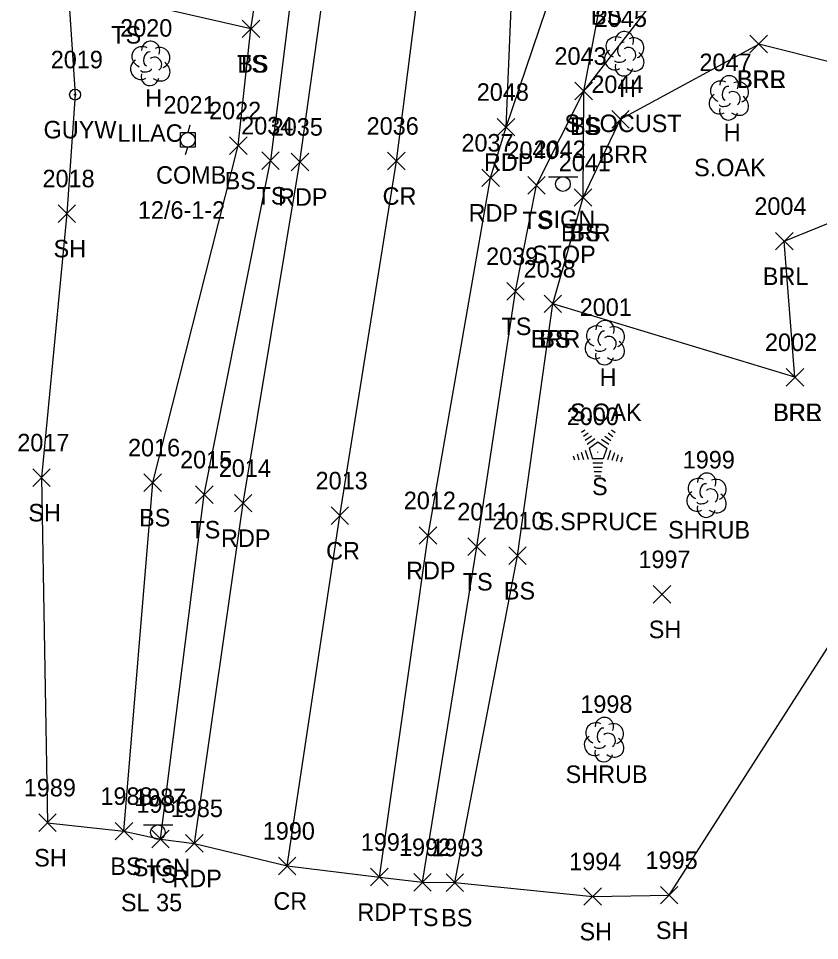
# Model space of a CAD drawing. Extents: x 1461855 to 1464118, y 556196 to 557441.
# Drawn here: x 1461894.8 to 1461986.2, y 556297.5 to 556402.7 of the extents above; entities that cross this region are included whole.
import ezdxf

# ---------------------------------------------------------------- set-up
doc = ezdxf.new("R2010")
doc.units = 0
for name, color, linetype in [('L_A', 7, 'Continuous'), ('L_C', 7, 'Continuous'), ('L_I', 7, 'Continuous'), ('L_TIC', 7, 'Continuous'), ('LABL', 7, 'Continuous'), ('LELB', 7, 'Continuous'), ('LSH', 7, 'Continuous'), ('LSOGP', 7, 'Continuous'), ('LTC', 7, 'Continuous'), ('LTD', 7, 'Continuous'), ('P_A', 7, 'Continuous'), ('P_I', 7, 'Continuous'), ('P_TIC', 7, 'Continuous'), ('PET', 7, 'Continuous'), ('PRC', 7, 'Continuous'), ('S_A', 7, 'Continuous'), ('S_C', 7, 'Continuous'), ('S_I', 7, 'Continuous'), ('SSGN', 7, 'Continuous'), ('U_A', 7, 'Continuous'), ('U_C', 7, 'Continuous'), ('U_I', 7, 'Continuous'), ('UP', 7, 'Continuous'), ('UPGW', 7, 'Continuous')]:
    doc.layers.add(name, color=color, linetype=linetype)

msp = doc.modelspace()

# ---------------------------------------------------------------- linework, layer by layer
at = {"layer": 'L_TIC'}
for points in [[(1461920.33, 556400.53), (1461922.33, 556402.53)], [(1461922.33, 556400.53), (1461920.33, 556402.53)], [(1461920.33, 556400.53), (1461922.33, 556402.53)], [(1461922.33, 556400.53), (1461920.33, 556402.53)], [(1461978.3, 556398.79), (1461980.3, 556400.79)], [(1461980.3, 556398.79), (1461978.3, 556400.79)], [(1461978.3, 556398.79), (1461980.3, 556400.79)], [(1461980.3, 556398.79), (1461978.3, 556400.79)], [(1461958.32, 556393.42), (1461960.32, 556395.42)], [(1461960.32, 556393.42), (1461958.32, 556395.42)], [(1461958.32, 556393.42), (1461960.32, 556395.42)], [(1461960.32, 556393.42), (1461958.32, 556395.42)], [(1461962.52, 556390.2), (1461964.52, 556392.2)], [(1461964.52, 556390.2), (1461962.52, 556392.2)], [(1461918.89, 556387.2), (1461920.89, 556389.2)], [(1461920.89, 556387.2), (1461918.89, 556389.2)], [(1461922.56, 556385.47), (1461924.56, 556387.47)], [(1461924.56, 556385.47), (1461922.56, 556387.47)], [(1461922.56, 556385.47), (1461924.56, 556387.47)], [(1461924.56, 556385.47), (1461922.56, 556387.47)], [(1461952.93, 556382.67), (1461954.93, 556384.67)], [(1461954.93, 556382.67), (1461952.93, 556384.67)], [(1461958.24, 556381.28), (1461960.24, 556383.28)], [(1461960.24, 556381.28), (1461958.24, 556383.28)], [(1461958.24, 556381.28), (1461960.24, 556383.28)], [(1461960.24, 556381.28), (1461958.24, 556383.28)], [(1461899.31, 556379.44), (1461901.31, 556381.44)], [(1461901.31, 556379.44), (1461899.31, 556381.44)], [(1461981.22, 556376.29), (1461983.22, 556378.29)], [(1461983.22, 556376.29), (1461981.22, 556378.29)], [(1461950.53, 556370.57), (1461952.53, 556372.57)], [(1461952.53, 556370.57), (1461950.53, 556372.57)], [(1461954.8, 556369.14), (1461956.8, 556371.14)], [(1461956.8, 556369.14), (1461954.8, 556371.14)], [(1461954.8, 556369.14), (1461956.8, 556371.14)], [(1461956.8, 556369.14), (1461954.8, 556371.14)], [(1461982.43, 556360.75), (1461984.43, 556362.75)], [(1461984.43, 556360.75), (1461982.43, 556362.75)], [(1461982.43, 556360.75), (1461984.43, 556362.75)], [(1461984.43, 556360.75), (1461982.43, 556362.75)], [(1461896.43, 556349.3), (1461898.43, 556351.3)], [(1461898.43, 556349.3), (1461896.43, 556351.3)], [(1461909.12, 556348.73), (1461911.12, 556350.73)], [(1461911.12, 556348.73), (1461909.12, 556350.73)], [(1461915.01, 556347.36), (1461917.01, 556349.36)], [(1461917.01, 556347.36), (1461915.01, 556349.36)], [(1461946.1, 556341.42), (1461948.1, 556343.42)], [(1461948.1, 556341.42), (1461946.1, 556343.42)], [(1461950.76, 556340.39), (1461952.76, 556342.39)], [(1461952.76, 556340.39), (1461950.76, 556342.39)], [(1461967.25, 556335.98), (1461969.25, 556337.98)], [(1461969.25, 556335.98), (1461967.25, 556337.98)], [(1461897.1, 556309.92), (1461899.1, 556311.92)], [(1461899.1, 556309.92), (1461897.1, 556311.92)], [(1461905.84, 556308.95), (1461907.84, 556310.95)], [(1461907.84, 556308.95), (1461905.84, 556310.95)], [(1461910.01, 556308.05), (1461912.01, 556310.05)], [(1461912.01, 556308.05), (1461910.01, 556310.05)], [(1461939.92, 556303.12), (1461941.92, 556305.12)], [(1461941.92, 556303.12), (1461939.92, 556305.12)], [(1461943.6, 556303.08), (1461945.6, 556305.08)], [(1461945.6, 556303.08), (1461943.6, 556305.08)], [(1461959.35, 556301.49), (1461961.35, 556303.49)], [(1461961.35, 556301.49), (1461959.35, 556303.49)], [(1461968.08, 556301.64), (1461970.08, 556303.64)], [(1461970.08, 556301.64), (1461968.08, 556303.64)]]:
    msp.add_lwpolyline(points, dxfattribs=at)
at = {"layer": 'LABL'}
for points in [[(1461983.43, 556361.75), (1461955.8, 556370.14), (1461959.24, 556382.28), (1461963.52, 556391.2), (1461979.3, 556399.79)], [(1461983.43, 556361.75), (1461982.22, 556377.29), (1461996.74, 556383.18), (1461996.43, 556395.47), (1461979.3, 556399.79)]]:
    msp.add_lwpolyline(points, dxfattribs=at)
at = {"layer": 'LELB'}
for points in [[(1461959.24, 556382.28), (1461959.32, 556394.42), (1461961.7, 556406.99), (1461971.62, 556419.74), (1461999.37, 556433.49)], [(1461921.33, 556401.53), (1461906.98, 556404.84), (1461899.53, 556420.36), (1461906.98, 556423.45), (1461923.2, 556423.61), (1461927.16, 556415.18), (1461923.56, 556386.47)], [(1461906.84, 556309.95), (1461910.12, 556349.73), (1461919.89, 556388.2), (1461921.33, 556401.53), (1461922.52, 556409.21), (1461920.13, 556420.53)], [(1461940.92, 556304.12), (1461947.1, 556342.42), (1461951.53, 556371.57), (1461953.93, 556383.67), (1461959.32, 556394.42), (1461975.32, 556415.02), (1461996.03, 556418.95)], [(1461911.01, 556309.05), (1461916.01, 556348.36), (1461923.56, 556386.47)], [(1461944.6, 556304.08), (1461951.76, 556341.39), (1461955.8, 556370.14)]]:
    msp.add_lwpolyline(points, dxfattribs=at)
at = {"layer": 'LSH'}
for p, q in [((1461973.32, 556348.35), (1461973.32, 556348.35)), ((1461973.32, 556348.35), (1461973.32, 556348.35)), ((1461961.62, 556320.45), (1461961.62, 556320.45)), ((1461961.62, 556320.45), (1461961.62, 556320.45))]:
    msp.add_line(p, q, dxfattribs=at)
for centre in [(1461973.36, 556349.78), (1461961.67, 556321.89)]:
    msp.add_arc(centre, 1.05, 335.5272, 180.9563, dxfattribs=at)
for centre, major_axis, ratio, start_param, end_param in [((1461972.53, 556349.01), (1.21, -0.51), 0.895232, 1.570796, 4.712389), ((1461973.11, 556348.81), (-0.208, -0.792), 0.645439, 3.141593, 6.283185), ((1461974.36, 556348.93), (-1.14, -0.48), 0.949671, 1.570796, 4.712389), ((1461972.23, 556347.64), (0.58, -1.04), 0.959034, 3.141593, 6.283185), ((1461973.82, 556348.18), (-0.5, 0.667), 0.989748, 3.141593, 6.283185), ((1461972.86, 556347.6), (-0.625, -0.083), 0.423636, 0, 3.141593), ((1461974.32, 556347.51), (-1.09, 0.79), 0.841452, 1.570796, 4.712389), ((1461973.32, 556346.85), (0.26, 1.06), 0.942809, 1.570796, 4.712389), ((1461960.83, 556321.12), (1.21, -0.51), 0.895232, 1.570796, 4.712389), ((1461962.66, 556321.04), (-1.14, -0.48), 0.949671, 1.570796, 4.712389), ((1461961.41, 556320.91), (-0.208, -0.792), 0.645439, 3.141593, 6.283185), ((1461960.54, 556319.75), (0.58, -1.04), 0.959034, 3.141593, 6.283185), ((1461962.12, 556320.29), (-0.5, 0.667), 0.989748, 3.141593, 6.283185), ((1461962.62, 556319.62), (-1.09, 0.79), 0.841452, 1.570796, 4.712389), ((1461961.62, 556318.95), (0.26, 1.06), 0.942809, 1.570796, 4.712389), ((1461961.16, 556319.7), (-0.625, -0.083), 0.423636, 0, 3.141593)]:
    msp.add_ellipse(centre, major_axis=major_axis, ratio=ratio, start_param=start_param, end_param=end_param, dxfattribs=at)
at = {"layer": 'LSOGP'}
msp.add_lwpolyline([(1461899.53, 556420.36), (1461901.26, 556394.02), (1461900.31, 556380.44), (1461897.43, 556350.3), (1461898.1, 556310.92), (1461906.84, 556309.95), (1461911.01, 556309.05), (1461914.87, 556308.56), (1461925.46, 556305.98), (1461935.99, 556304.71), (1461940.92, 556304.12), (1461944.6, 556304.08), (1461960.35, 556302.49), (1461969.08, 556302.64), (1461988.94, 556333.66), (1462002.21, 556358.85), (1462020.07, 556368.85), (1462042.96, 556370.97)], dxfattribs=at)
at = {"layer": 'LTC'}
for p, q in [((1461959.08, 556355.5), (1461959.43, 556355.76)), ((1461959.29, 556355.04), (1461959.82, 556355.42)), ((1461959.5, 556354.57), (1461960.2, 556355.08)), ((1461961.73, 556355.05), (1461962.41, 556354.55)), ((1461962.11, 556355.4), (1461962.66, 556355)), ((1461962.48, 556355.75), (1461962.9, 556355.44)), ((1461959.71, 556354.11), (1461960.59, 556354.75)), ((1461959.93, 556353.65), (1461960.94, 556354.39)), ((1461960.94, 556354.39), (1461961.94, 556353.66)), ((1461961.36, 556354.7), (1461962.17, 556354.11)), ((1461958.57, 556353), (1461958.78, 556352.35)), ((1461959.02, 556353.22), (1461959.29, 556352.38)), ((1461959.48, 556353.43), (1461959.81, 556352.41)), ((1461959.93, 556353.65), (1461960.32, 556352.46)), ((1461961.94, 556353.66), (1461961.55, 556352.46)), ((1461962.38, 556353.39), (1461962.04, 556352.35)), ((1461962.82, 556353.14), (1461962.54, 556352.26)), ((1461963.27, 556352.89), (1461963.03, 556352.16)), ((1461958.11, 556352.78), (1461958.26, 556352.32)), ((1461961.55, 556352.46), (1461960.32, 556352.46)), ((1461961.51, 556351.96), (1461960.37, 556351.96)), ((1461963.71, 556352.64), (1461963.52, 556352.07)), ((1461961.43, 556351.46), (1461960.44, 556351.46)), ((1461961.34, 556350.96), (1461960.51, 556350.96)), ((1461961.26, 556350.46), (1461960.58, 556350.46))]:
    msp.add_line(p, q, dxfattribs=at)
at = {"layer": 'LTD'}
for p, q in [((1461963.93, 556398.74), (1461963.93, 556398.74)), ((1461963.93, 556398.74), (1461963.93, 556398.74)), ((1461909.82, 556397.63), (1461909.82, 556397.63)), ((1461909.82, 556397.63), (1461909.82, 556397.63)), ((1461975.87, 556393.7), (1461975.87, 556393.7)), ((1461975.87, 556393.7), (1461975.87, 556393.7)), ((1461961.71, 556365.76), (1461961.71, 556365.76)), ((1461961.71, 556365.76), (1461961.71, 556365.76))]:
    msp.add_line(p, q, dxfattribs=at)
for centre in [(1461963.97, 556400.17), (1461909.87, 556399.06), (1461975.92, 556395.13), (1461961.75, 556367.19)]:
    msp.add_arc(centre, 1.05, 335.5272, 180.9563, dxfattribs=at)
for centre, major_axis, ratio, start_param, end_param in [((1461963.14, 556399.41), (1.21, -0.51), 0.895232, 1.570796, 4.712389), ((1461964.97, 556399.32), (-1.14, -0.48), 0.949671, 1.570796, 4.712389), ((1461909.03, 556398.29), (1.21, -0.51), 0.895232, 1.570796, 4.712389), ((1461910.86, 556398.21), (-1.14, -0.48), 0.949671, 1.570796, 4.712389), ((1461963.72, 556399.2), (-0.208, -0.792), 0.645439, 3.141593, 6.283185), ((1461964.43, 556398.57), (-0.5, 0.667), 0.989748, 3.141593, 6.283185), ((1461909.61, 556398.09), (-0.208, -0.792), 0.645439, 3.141593, 6.283185), ((1461910.32, 556397.46), (-0.5, 0.667), 0.989748, 3.141593, 6.283185), ((1461962.84, 556398.03), (0.58, -1.04), 0.959034, 3.141593, 6.283185), ((1461964.93, 556397.91), (-1.09, 0.79), 0.841452, 1.570796, 4.712389), ((1461908.74, 556396.92), (0.58, -1.04), 0.959034, 3.141593, 6.283185), ((1461910.82, 556396.79), (-1.09, 0.79), 0.841452, 1.570796, 4.712389), ((1461963.93, 556397.24), (0.26, 1.06), 0.942809, 1.570796, 4.712389), ((1461963.47, 556397.99), (-0.625, -0.083), 0.423636, 0, 3.141593), ((1461909.82, 556396.13), (0.26, 1.06), 0.942809, 1.570796, 4.712389), ((1461909.36, 556396.88), (-0.625, -0.083), 0.423636, 0, 3.141593), ((1461975.08, 556394.37), (1.21, -0.51), 0.895232, 1.570796, 4.712389), ((1461975.66, 556394.16), (-0.208, -0.792), 0.645439, 3.141593, 6.283185), ((1461976.91, 556394.28), (-1.14, -0.48), 0.949671, 1.570796, 4.712389), ((1461974.79, 556392.99), (0.58, -1.04), 0.959034, 3.141593, 6.283185), ((1461976.37, 556393.53), (-0.5, 0.667), 0.989748, 3.141593, 6.283185), ((1461975.41, 556392.95), (-0.625, -0.083), 0.423636, 0, 3.141593), ((1461976.87, 556392.87), (-1.09, 0.79), 0.841452, 1.570796, 4.712389), ((1461975.87, 556392.2), (0.26, 1.06), 0.942809, 1.570796, 4.712389), ((1461960.92, 556366.42), (1.21, -0.51), 0.895232, 1.570796, 4.712389), ((1461962.75, 556366.34), (-1.14, -0.48), 0.949671, 1.570796, 4.712389), ((1461961.5, 556366.22), (-0.208, -0.792), 0.645439, 3.141593, 6.283185), ((1461962.21, 556365.59), (-0.5, 0.667), 0.989748, 3.141593, 6.283185), ((1461960.62, 556365.05), (0.58, -1.04), 0.959034, 3.141593, 6.283185), ((1461962.71, 556364.92), (-1.09, 0.79), 0.841452, 1.570796, 4.712389), ((1461961.71, 556364.26), (0.26, 1.06), 0.942809, 1.570796, 4.712389), ((1461961.25, 556365.01), (-0.625, -0.083), 0.423636, 0, 3.141593)]:
    msp.add_ellipse(centre, major_axis=major_axis, ratio=ratio, start_param=start_param, end_param=end_param, dxfattribs=at)
at = {"layer": 'P_TIC'}
for points in [[(1461949.45, 556389.31), (1461951.45, 556391.31)], [(1461951.45, 556389.31), (1461949.45, 556391.31)], [(1461949.45, 556389.31), (1461951.45, 556391.31)], [(1461951.45, 556389.31), (1461949.45, 556391.31)], [(1461925.93, 556385.33), (1461927.93, 556387.33)], [(1461927.93, 556385.33), (1461925.93, 556387.33)], [(1461936.93, 556385.44), (1461938.93, 556387.44)], [(1461938.93, 556385.44), (1461936.93, 556387.44)], [(1461947.69, 556383.52), (1461949.69, 556385.52)], [(1461949.69, 556383.52), (1461947.69, 556385.52)], [(1461919.44, 556346.39), (1461921.44, 556348.39)], [(1461921.44, 556346.39), (1461919.44, 556348.39)], [(1461930.48, 556344.96), (1461932.48, 556346.96)], [(1461932.48, 556344.96), (1461930.48, 556346.96)], [(1461940.55, 556342.7), (1461942.55, 556344.7)], [(1461942.55, 556342.7), (1461940.55, 556344.7)], [(1461913.87, 556307.56), (1461915.87, 556309.56)], [(1461915.87, 556307.56), (1461913.87, 556309.56)], [(1461924.46, 556304.98), (1461926.46, 556306.98)], [(1461926.46, 556304.98), (1461924.46, 556306.98)], [(1461934.99, 556303.71), (1461936.99, 556305.71)], [(1461936.99, 556303.71), (1461934.99, 556305.71)]]:
    msp.add_lwpolyline(points, dxfattribs=at)
at = {"layer": 'PET'}
for points in [[(1461914.87, 556308.56), (1461920.44, 556347.39), (1461926.93, 556386.33), (1461932.33, 556425.02), (1461933.9, 556440.31), (1461936.11, 556466.53), (1461937.59, 556495.16), (1461939.4, 556524.21), (1461940.1, 556552.33), (1461938.36, 556576.02), (1461936.48, 556592.89), (1461931.2, 556609.96), (1461922.6, 556632.21)], [(1461935.99, 556304.71), (1461941.55, 556343.7), (1461948.69, 556384.52), (1461950.45, 556390.31), (1461951.97, 556426.62), (1461954.17, 556443.19), (1461955.34, 556466.86), (1461956.95, 556490.65)], [(1461950.45, 556390.31), (1461956.54, 556408.29), (1461967.75, 556423.86), (1461995.49, 556440.02), (1462019.68, 556443.95), (1462033.02, 556445.73), (1462048.81, 556444.89)]]:
    msp.add_lwpolyline(points, dxfattribs=at)
at = {"layer": 'PRC'}
msp.add_lwpolyline([(1461925.46, 556305.98), (1461931.48, 556345.96), (1461937.93, 556386.44), (1461943.12, 556427.08), (1461945.49, 556465.38), (1461946.96, 556493.02), (1461948.29, 556523.84), (1461949.6, 556552.44), (1461949.09, 556575.71), (1461945.13, 556594.53), (1461941.15, 556612.68), (1461941.74, 556618.09), (1461960.04, 556581.27), (1461976.53, 556548.03), (1461990.31, 556523.95), (1462006.12, 556501.89), (1462023.43, 556483.27), (1462041.85, 556469.09), (1462061.76, 556457.44), (1462082.72, 556450.2), (1462107.82, 556443.98), (1462129.57, 556440.39), (1462147.93, 556438.2)], dxfattribs=at)
at = {"layer": 'SSGN'}
for p, q in [((1461955.31, 556384.64), (1461958.64, 556384.64)), ((1461956.95, 556383.81), (1461956.95, 556383.81)), ((1461909.06, 556310.66), (1461912.4, 556310.66)), ((1461910.71, 556309.83), (1461910.71, 556309.83))]:
    msp.add_line(p, q, dxfattribs=at)
for centre in [(1461956.95, 556383.81), (1461910.71, 556309.83)]:
    msp.add_circle(centre, 0.833, dxfattribs=at)
at = {"layer": 'UP'}
for p, q in [((1461913.29, 556388.02), (1461913.29, 556389.69)), ((1461913.29, 556389.69), (1461914.95, 556389.69)), ((1461914.37, 556390.52), (1461914.12, 556389.69)), ((1461914.95, 556389.69), (1461914.95, 556388.02)), ((1461914.12, 556388.85), (1461914.12, 556388.85)), ((1461914.95, 556388.02), (1461913.29, 556388.02)), ((1461913.87, 556387.19), (1461914.12, 556388.02))]:
    msp.add_line(p, q, dxfattribs=at)
msp.add_circle((1461914.12, 556388.85), 0.833, dxfattribs=at)
at = {"layer": 'UPGW'}
for radius in [0.625, 0.0833]:
    msp.add_circle((1461901.26, 556394.02), radius, dxfattribs=at)

# ---------------------------------------------------------------- texts
at = {"layer": 'L_A'}
for s, p in [('BS', (1461960.14, 556401.99)), ('TS', (1461905.39, 556399.84)), ('TS', (1461919.74, 556396.53)), ('BS', (1461919.77, 556396.53)), ('BRR', (1461976.79, 556394.79)), ('BRL', (1461976.84, 556394.79)), ('H', (1461963.36, 556393.74)), ('H', (1461909.26, 556392.63)), ('TS', (1461957.73, 556389.42)), ('BS', (1461957.76, 556389.42)), ('H', (1461975.3, 556388.7)), ('BRR', (1461961.01, 556386.2)), ('BS', (1461918.33, 556383.2)), ('TS', (1461921.97, 556381.47)), ('TS', (1461921.97, 556381.47)), ('TS', (1461952.34, 556378.67)), ('BRR', (1461956.73, 556377.28)), ('BS', (1461957.68, 556377.28)), ('SH', (1461898.8, 556375.44)), ('BRL', (1461979.76, 556372.29)), ('TS', (1461949.93, 556366.57)), ('BRR', (1461953.28, 556365.14)), ('BS', (1461954.24, 556365.14)), ('H', (1461961.14, 556360.76)), ('BRR', (1461980.92, 556356.75)), ('BRL', (1461980.97, 556356.75)), ('S', (1461960.27, 556348.3)), ('SH', (1461895.92, 556345.3)), ('BS', (1461908.56, 556344.73)), ('TS', (1461914.42, 556343.36)), ('SHRUB', (1461968.95, 556343.35)), ('TS', (1461945.51, 556337.42)), ('BS', (1461950.2, 556336.39)), ('SH', (1461966.74, 556331.98)), ('SHRUB', (1461957.25, 556315.45)), ('SH', (1461896.59, 556305.92)), ('BS', (1461905.28, 556304.95)), ('TS', (1461909.42, 556304.05)), ('TS', (1461939.33, 556299.12)), ('BS', (1461943.04, 556299.08)), ('SH', (1461958.84, 556297.49)), ('SH', (1461967.56, 556297.64))]:
    msp.add_text(s, height=2, dxfattribs=at).set_placement(p)
at = {"layer": 'L_C'}
for s, p in [('S.LOCUST', (1461957.12, 556389.74)), ('LILAC', (1461906.1, 556388.63)), ('S.OAK', (1461971.92, 556384.7)), ('S.OAK', (1461957.76, 556356.76)), ('S.SPRUCE', (1461954.1, 556344.3))]:
    msp.add_text(s, height=2, dxfattribs=at).set_placement(p)
at = {"layer": 'L_I'}
for s, p in [('2045', (1461960.59, 556401.74)), ('2020', (1461906.4, 556400.63)), ('2043', (1461955.98, 556397.42)), ('2043', (1461955.98, 556397.42)), ('2047', (1461972.53, 556396.7)), ('2044', (1461960.19, 556394.2)), ('2022', (1461916.55, 556391.2)), ('2034', (1461920.22, 556389.47)), ('2034', (1461920.22, 556389.47)), ('2040', (1461950.5, 556386.67)), ('2041', (1461956.47, 556385.28)), ('2041', (1461956.47, 556385.28)), ('2018', (1461897.54, 556383.44)), ('2004', (1461978.8, 556380.29)), ('2039', (1461948.18, 556374.57)), ('2038', (1461952.46, 556373.14)), ('2038', (1461952.46, 556373.14)), ('2001', (1461958.86, 556368.76)), ('2002', (1461980.01, 556364.75)), ('2002', (1461980.01, 556364.75)), ('2000', (1461957.38, 556356.3)), ('2017', (1461894.66, 556353.3)), ('2016', (1461907.3, 556352.73)), ('2015', (1461913.24, 556351.36)), ('1999', (1461970.62, 556351.35)), ('2011', (1461944.89, 556345.42)), ('2010', (1461948.9, 556344.39)), ('1997', (1461965.56, 556339.98)), ('1998', (1461958.93, 556323.45)), ('1989', (1461895.4, 556313.92)), ('1988', (1461904.15, 556312.95)), ('1986', (1461908.26, 556312.05)), ('1992', (1461938.23, 556307.12)), ('1993', (1461941.91, 556307.08)), ('1995', (1461966.38, 556305.64)), ('1994', (1461957.66, 556305.49))]:
    msp.add_text(s, height=2, dxfattribs=at).set_placement(p)
at = {"layer": 'LTC'}
msp.add_text('.', height=1.04, rotation=270, dxfattribs=at).set_placement((1461960.83, 556353.4))
at = {"layer": 'P_A'}
for s, p in [('RDP', (1461947.93, 556385.31)), ('RDP', (1461947.93, 556385.31)), ('CR', (1461936.36, 556381.44)), ('RDP', (1461924.42, 556381.33)), ('RDP', (1461946.18, 556379.52)), ('RDP', (1461917.92, 556342.39)), ('CR', (1461929.91, 556340.96)), ('RDP', (1461939.04, 556338.7)), ('RDP', (1461912.36, 556303.56)), ('CR', (1461923.89, 556300.98)), ('RDP', (1461933.48, 556299.71))]:
    msp.add_text(s, height=2, dxfattribs=at).set_placement(p)
at = {"layer": 'P_I'}
for s, p in [('2048', (1461947.11, 556393.31)), ('2048', (1461947.11, 556393.31)), ('2035', (1461923.59, 556389.33)), ('2036', (1461934.54, 556389.44)), ('2037', (1461945.36, 556387.52)), ('2014', (1461917.66, 556350.39)), ('2013', (1461928.71, 556348.96)), ('2012', (1461938.78, 556346.7)), ('1985', (1461912.18, 556311.56)), ('1990', (1461922.68, 556308.98)), ('1991', (1461933.87, 556307.71))]:
    msp.add_text(s, height=2, dxfattribs=at).set_placement(p)
at = {"layer": 'S_A'}
for p in [(1461954.09, 556378.78), (1461907.85, 556304.81)]:
    msp.add_text('SIGN', height=2, dxfattribs=at).set_placement(p)
at = {"layer": 'S_C'}
for s, p in [('STOP', (1461953.41, 556374.78)), ('SL 35', (1461906.49, 556300.81))]:
    msp.add_text(s, height=2, dxfattribs=at).set_placement(p)
at = {"layer": 'S_I'}
for s, p in [('2042', (1461953.6, 556386.78)), ('1987', (1461908, 556312.81))]:
    msp.add_text(s, height=2, dxfattribs=at).set_placement(p)
at = {"layer": 'U_A'}
for s, p in [('GUYW', (1461897.66, 556389.02)), ('COMB', (1461910.5, 556383.85))]:
    msp.add_text(s, height=2, dxfattribs=at).set_placement(p)
at = {"layer": 'U_C'}
msp.add_text('12/6-1-2', height=2, dxfattribs=at).set_placement((1461908.43, 556379.85))
at = {"layer": 'U_I'}
for s, p in [('2019', (1461898.48, 556397.02)), ('2021', (1461911.35, 556391.85))]:
    msp.add_text(s, height=2, dxfattribs=at).set_placement(p)

doc.saveas('drawing.dxf')
